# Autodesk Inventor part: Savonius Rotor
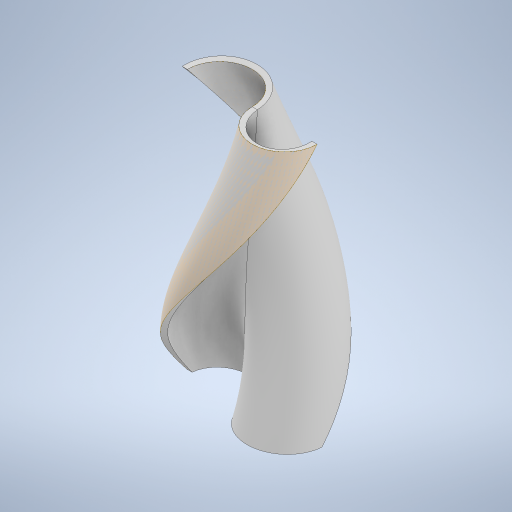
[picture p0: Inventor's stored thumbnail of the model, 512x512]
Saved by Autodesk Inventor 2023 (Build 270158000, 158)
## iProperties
Created: 2025-05
Part Number: Savonius Rotor
Material: Generic
Document SubType Name: Modeling
Designer: Brecht.Carpentier
Density: 1 g/cm^3
Appearance: Default
Author: Brecht.Carpentier
## Parameters: d6 = 25 mm, d7 = 0, d8 = 12.5 mm, d9 = 12.5 mm, d10 = 6.25 mm, d11 = 0, d12 = 0, d13 = 1 mm, d14 = 1 mm
